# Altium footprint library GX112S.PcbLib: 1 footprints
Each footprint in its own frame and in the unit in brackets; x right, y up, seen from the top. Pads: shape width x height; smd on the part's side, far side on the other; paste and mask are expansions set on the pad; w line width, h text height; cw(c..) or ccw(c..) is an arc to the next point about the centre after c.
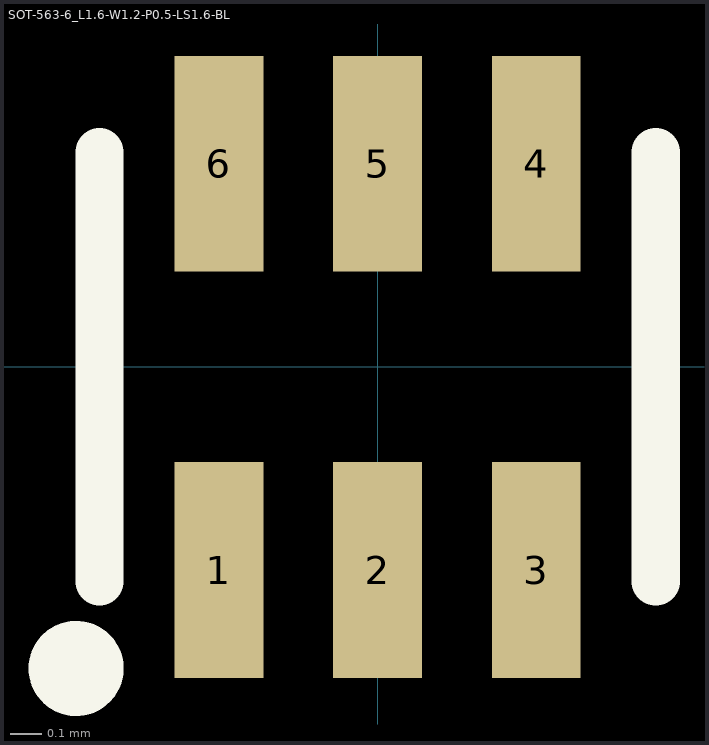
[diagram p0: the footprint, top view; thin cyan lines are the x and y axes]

## SOT-563-6_L1.6-W1.2-P0.5-LS1.6-BL [mm]
pads (6):
  rect 0.28x0.68 smd: 1(-0.5,-0.64) 2(0,-0.64) 3(0.5,-0.64) 4(0.5,0.64) 5(0,0.64) 6(-0.5,0.64)
Top Overlay:
  circle w0.15: c-0.95,-0.95 r0.075
  lines w0.152: -0.876,-0.676 -0.876,0.676 ; 0.876,-0.676 0.876,0.676
3D body "SOT563-6.STEP": height 0.56, standoff 0, extent -0.813,-0.8 0.787,0.8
